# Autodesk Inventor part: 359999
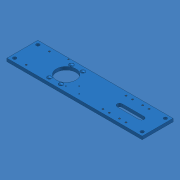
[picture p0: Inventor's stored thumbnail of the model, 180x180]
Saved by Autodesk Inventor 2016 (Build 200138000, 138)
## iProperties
Company: Mayer & Müller AG Schaltgeräte
Created: 2017-05
Part Number: 359999
Material: 1.0120
Document SubType Name: Modeling
Designer: I.Baliuc
Manufacturer: Standard
Standards Organization: Custom
Description: Seitenteil, Trenner
Cost Center: 5,196 kg
Authority: 661896 mm^3
Density: 7.85 g/cm^3
Appearance: RAL 5012 Lichtblau
HalbzeugNorm: DIN 174
Zweck: HSLT / HSE - Standardseite
Abmessung: Fl. 120x12-170
SaveDate: 2006-10-28
SaveTime: 20:23
TotalMass: 5,196 kg
TotalVolume: 661896 mm^3
Kopiert_von_Autor: CH
Kopie_erstellt_am: 2017-05-01T13:09:13
Kopiert_von_Datei: D:\Inventor-Tools Tutorial\Bauteile\3\36\364835 Seitenteil.ipt
Kopie_Zieldatei: D:\Inventor-Tools Tutorial\Bauteile\3\35\359999.ipt
Author: CH
Keywords: 380125
Revision Number: 364845
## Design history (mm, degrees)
sketch "Skizze2"
  geometry: L1 (-170, 60)-(355, 60); L2 (355, 60)-(355, -60); L3 (355, -60)-(-170, -60); L4 (-170, -60)-(-170, 60); L5 (-222.5, 0)-(512.5, 0) reference; L6 (0, -72)-(0, 96) reference; L7 (292.5, 10)-(207.5, 10); L8 (207.5, -10)-(292.5, -10); C1 r 38 at (0, 0); A1 r 10 centre (292.5, 0) between (292.5, -10) and (292.5, 10); A2 r 10 centre (207.5, 0) between (207.5, 10) and (207.5, -10)
  constraints: 12 end point, 4 point on circle, 4 point on line, 3 centre point, 3 parallel, 2 tangent, 1 horizontal, 1 perpendicular, 2 other
  dimensions: "d4" = 170 distance between parallel lines of L4 L6; "d5" = 525 distance of L1.start L1.end; "d6" = 120 distance of L3.end L1.start; "d7" = 76 diameter of C1; "d8" = 85 distance of A2.centre A1.centre; "d9" = 20 distance between parallel lines of L7 L8; "d10" = 62.5 distance from line of L2 A1.centre
extrude "Extrusion2" new body sketch "Skizze2" distance "d11" = 12; taper "d12" = 0 deg
sketch "Skizze3"
  geometry: L1 (355, 60)-(355, -60) reference; L2 (-170, -60)-(-170, 60) reference; L3 (-222.5, 0)-(512.5, 0) reference; 4 further points
  constraints: 2 symmetric about line
  dimensions: "d13" = 90 distance of point (-155, -45) point (-155, 45); "d14" = 15 distance from line of point (-155, 45) L2; "d15" = 90 distance of point (340, -45) point (340, 45) (= d13); "d16" = 15 distance from line of point (340, 45) L1 (= d14)
hole "Bohrung_Ø13" sketch "Skizze3" at (-155, 45), (-155, -45), (340, -45), (340, 45) diameter "d17" = 13; stored, may be unused: countersink angle "d21" = 90 deg, drill point angle "d23" = 118 deg; dims "d18" = 6, "d19" = 4, "d20" = 2, "d22" = 8
sketch "Skizze4"
  geometry: L1 (-222.5, 0)-(512.5, 0) reference; L2 (0, -72)-(0, 96) reference; 4 further points
  constraints: 3 symmetric about line
  dimensions: "d24" = 85 distance of point (22.5, -42.5) point (22.5, 42.5); "d25" = 45 distance of point (-22.5, 42.5) point (22.5, 42.5)
hole "Bohrung2" sketch "Skizze4" at (22.5, 42.5), (22.5, -42.5), (-22.5, -42.5), (-22.5, 42.5) diameter "d26" = 16.5; stored, may be unused: countersink angle "d30" = 90 deg, drill point angle "d32" = 0 deg; dims "d27" = 6, "d28" = 16.5, "d29" = 0.4, "d31" = 0.7
sketch "Skizze5"
  geometry: C1 r 8.25 at (0, 0) reference; C2 r 8.25 at (0, -85) reference; C3 r 8.25 at (45, -85) reference; C4 r 8.25 at (45, 0) reference; 4 further points
  constraints: 4 coincident
hole "Bohrung3" sketch "Skizze5" at (0, 0), (45, 0), (45, -85), (0, -85) diameter "d33" = 8.4; stored, may be unused: countersink angle "d37" = 90 deg, drill point angle "d39" = 118 deg; dims "d34" = 6, "d35" = 16.5 (= d26), "d36" = 2, "d38" = 8
sketch "Skizze6"
  geometry: L1 (-170, -60)-(-170, 60) reference; L2 (-222.5, 0)-(512.5, 0) reference; 2 further points
  constraints: 1 symmetric about line
  dimensions: "d40" = 90 distance of point (-110, -45) point (-110, 45); "d41" = 60 distance from line of point (-110, 45) L1
hole "Bohrung_M8_01" sketch "Skizze6" at (-110, 45), (-110, -45) diameter "d42" = 6.647; stored, may be unused: countersink angle "d46" = 90 deg, drill point angle "d48" = 118 deg; dims "d43" = 6, "d44" = 4, "d45" = 2, "d47" = 8
sketch "Skizze7"
  geometry: L1 (355, 60)-(355, -60) reference; L2 (-170, 60)-(355, 60) reference; L3 (-222.5, 0)-(512.5, 0) reference; 4 further points
  constraints: 1 horizontal, 1 vertical, 3 other
  dimensions: "d49" = 90 diameter of point (277, 45) L3; "d50" = 78 distance from line of L1 point (277, 45); "d53" = 90 distance of point (277, 45) point (277, -45) (= d49); "d56" = 25 distance of point (277, 45) point (252, 45)
hole "Bohrung_M8_02" sketch "Skizze7" at (277, 45), (277, -45), (252, 45), (252, -45) diameter "d59" = 6.647; stored, may be unused: countersink angle "d63" = 90 deg, drill point angle "d65" = 118 deg; dims "d60" = 6, "d61" = 4, "d62" = 2, "d64" = 8
hole "Bohrung_M6" diameter "d68" = 4.917; stored, may be unused: countersink angle "d72" = 90 deg, drill point angle "d74" = 118 deg; dims "d66" = 401, "d67" = 5, "d69" = 6, "d70" = 4, "d71" = 2, "d73" = 8
sketch "Skizze8"
  geometry: L1 (355, -60)-(-170, -60) reference; L2 (90.5, -40)-(38.5, -40); L3 (64.5, -14)-(64.5, -80.919); C1 r 38 at (0, 0) reference; 3 further points
  constraints: 4 end point, 3 coincident, 1 parallel, 1 perpendicular, 1 symmetric about line
  dimensions: "d75" = 26 distance from line of L3 point (38.5, -40); "d76" = 26 distance from line of L3 point (90.5, -40) (derived); "d77" = 26 distance from line of L2 point (64.5, -14); "d78" = 40 distance from line of L2 C1.centre; "d79" = 64.5 distance from line of L3 C1.centre
hole "Bohrung_M5" sketch "Skizze8" at (64.5, -14), (90.5, -40), (38.5, -40) diameter "d80" = 4.134; stored, may be unused: countersink angle "d84" = 90 deg, drill point angle "d86" = 118 deg; dims "d81" = 6, "d82" = 4, "d83" = 2, "d85" = 8
pattern_linear "Neue Bohrung (zusätzlich)" dims "d89" = 64.5
node "Center of Mass"
node "Volumenkörper1"
node "Volumenkörpern"
node "Oberflächenkörpern"
node "Projizierte Kontur1"
